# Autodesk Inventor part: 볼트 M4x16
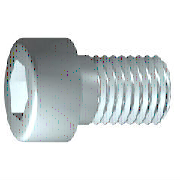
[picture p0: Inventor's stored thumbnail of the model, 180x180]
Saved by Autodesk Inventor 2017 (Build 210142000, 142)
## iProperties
IsCustomPart: 1
Created: 2012-02
Part Number: 볼트 M4x16
Material: 강철, 연강
Description: 6각머리 태핑 나사
Document SubType Name: Modeling
Standard: KS B 1003
Designer: mduedu
Standards Organization: KS
Language: ko-KR
Size Designation: M 4 x 16
Categories: <MemberInstance><Categories><Category DisplayName="조임쇠" InternalName="e4da775c-781d-43d5-af7c-5136215cf5a6" Mnemonic="FSTN"><Category DisplayName="볼트" InternalN
Density: 1 g/cm^3
Appearance: 강철
Author: mduedu
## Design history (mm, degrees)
sketch "스케치1"
  geometry: L1 (-1, 0)-(16, 0); L2 (16, 0)-(16, 2); L3 (16, 2)-(1.75, 2); L4 (1.75, 2)-(1.32, 2); L5 (1.32, 2)-(0, 2); L6 (0, 2)-(0, 3.5); L7 (0, 3.5)-(-4, 3.5); L8 (-4, 3.5)-(-4, 1.732); L9 (-4, 1.732)-(-2, 1.732); L10 (-2, 1.732)-(-1, 0); L11 (-8, 0)-(20, 0) reference; L12 (0, -0.7)-(0, 4.2) reference; L13 (1.75, 2)-(0, 2)
  constraints: 22 end point, 6 parallel, 2 collinear, 2 perpendicular, 1 horizontal, 1 point on line
  dimensions: "d1" = 14.25 distance from line of L3.end L2 (= GEL); "d2" = 0.42952 distance of L4.end L3.end (computed from GAL); "d3" = 4 distance between parallel lines of L8 L6 (= KOH); "d4" = 2 distance of L8.end L9.end (= INTI); "d5" = 60 deg angle of L10 L1; "d6" = 4 diameter of L3 L1 (= GD); "d7" = 4 diameter of L5 L1 (= BDM); "d8" = 3.4641 diameter of L9 L1 (= 1.1547 x SW); "d9" = 7 diameter of L7 L1 (= KOD); "d26" = 16 distance between parallel lines of L12 L2 (= NLG)
revolve "본체" sketch "스케치1" stored, may be unused: angle "d10" = 90 deg
sketch "스케치2"
  geometry: L1 (0, -4.9)-(0, 4.9) reference; L2 (-4.9, 0)-(4.9, 0) reference; L3 (1.732, 0)-(0.866, -1.5); L4 (0.866, -1.5)-(-0.866, -1.5); L5 (-0.866, -1.5)-(-1.732, 0); L6 (-1.732, 0)-(-0.866, 1.5); L7 (-0.866, 1.5)-(0.866, 1.5); L8 (0.866, 1.5)-(1.732, 0); 2 further points
  constraints: 12 end point, 1 coincident, 1 horizontal alignment, 1 point on line, 12 other
extrude "슬롯" join sketch "스케치2" stored distance "d11" = 10; taper "d12" = 0 deg
workplane "Work Plane1"
fillet "Fillet2" dims "d30" = 0.1 (= R)
body "Solid1"
fillet "모깎기1" dims "d17" = 0.4 (= RR)
feature "스레드" dims "d13" = 14.25 (= GEL), "d14" = 0
chamfer "모따기1" distance "d15" = 0.42941 (= -0.5 x SPD + 0.5 x GD); stored, may be unused: second distance "d16" = 0.42941 (= GUL), angle "d27" = 45 deg
other parameters: "GD" = 4 (= NND) [user parameter; used in 2 equation terms], "NLG" = 16 [user parameter; used in 1 equation term], "GEL" = 14.25 [user parameter; used in 2 equation terms], "KOD" = 7 [user parameter; used in 1 equation term], "KOH" = 4 [user parameter; used in 1 equation term], "INTI" = 2 [user parameter; used in 1 equation term], "GAL" = 0.42941 (= 0.61345 x PTC) [user parameter; used in 1 equation term], "GUL" = 0.42941 (= 0.61345 x PTC) [user parameter; used in 1 equation term], "BDM" = 4 (= NND) [user parameter; used in 1 equation term], "SW" = 3 [user parameter; used in 2 equation terms], "RR" = 0.4 [user parameter; used in 1 equation term], "SPD" = 3.14117 (= NND - 1.2269 x PTC) [user parameter; used in 1 equation term], "d19" = 0, "d28" = 0, "d29" = 0, "R" = 0.1 [user parameter; used in 1 equation term], "PHH" = 0.2 [user parameter], "GD1" = 3.14117 (= THREADDIA - 1.2269 x PTC) [user parameter], "THREADDIA" = 4 [user parameter; used in 1 equation term], "FAWI" = 45 deg [user parameter], "TPU" = 14.28571 (computed from PTC) [user parameter], "PTC" = 0.7 [user parameter; used in 5 equation terms], "NND" = 4 [user parameter; used in 3 equation terms], "TOA" = 30 deg [user parameter], "E0" = 3.465 (= 1.155 x SW) [user parameter]
